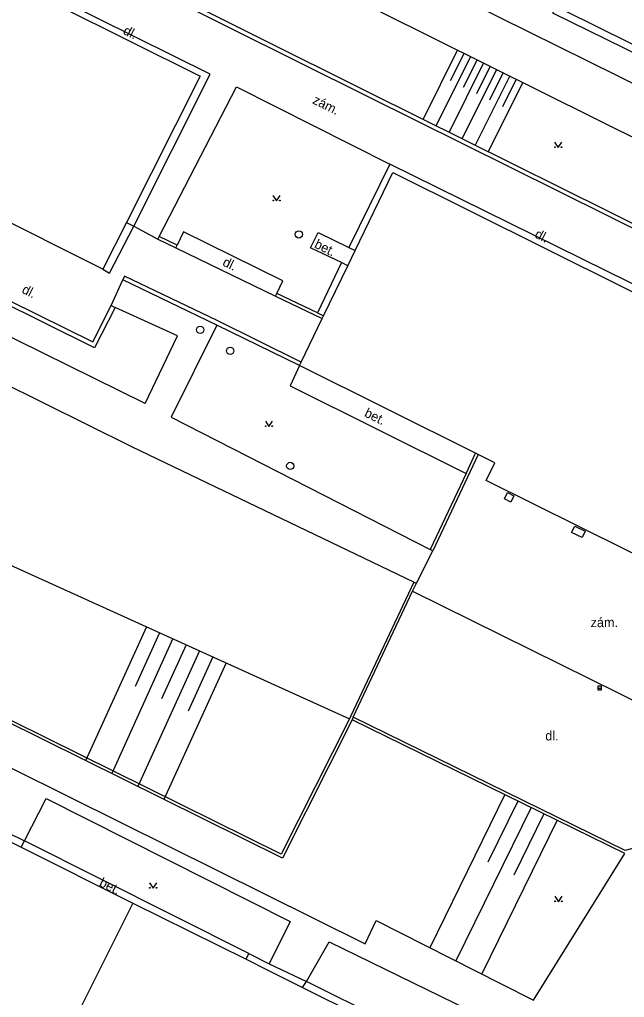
# Model space of a CAD drawing. Extents: x -602419 to -601554, y -1162937 to -1162362.
# Drawn here: x -602116.3 to -602074.8, y -1162567.9 to -1162500.8 of the extents above; entities that cross this region are included whole.
import ezdxf

# ---------------------------------------------------------------- set-up
doc = ezdxf.new("R2010")
doc.units = 0
doc.layers.add('Podklad', color=7, linetype='Continuous')

msp = doc.modelspace()

# ---------------------------------------------------------------- linework, layer by layer
at = {"layer": 'Podklad'}
msp.add_line((-602076.615, -1162546.67), (-602076.365, -1162546.67), dxfattribs=at)
for points in [[(-602089.26, -1162539.4), (-602108.58, -1162530.12), (-602154.26, -1162507.48), (-602198.48, -1162485.59), (-602249.5, -1162460.39)], [(-602093.5, -1162548.86), (-602098.27, -1162558.35), (-602128.4, -1162543.44), (-602175.25, -1162520.19), (-602211.34, -1162502.17), (-602258.9099, -1162478.56)], [(-602113.88, -1162489.1), (-602073.08, -1162509.4099)], [(-602072.35, -1162503.94), (-602079.7, -1162500.33), (-602078.6, -1162498.12), (-602081.55, -1162496.61), (-602082.2199, -1162497.76), (-602085.09, -1162496.3), (-602088.1599, -1162494.82), (-602087.5, -1162493.6599), (-602090.6, -1162492.15), (-602091.74, -1162494.33), (-602098.88, -1162490.82)], [(-602073.2, -1162505.6599), (-602099.7199, -1162492.51)], [(-602116.15, -1162493.87), (-602092.27, -1162505.8), (-602069.33, -1162517.19)], [(-602116.28, -1162494.14), (-602092.4099, -1162506.06), (-602069.46, -1162517.46)], [(-602209.38, -1162496.3), (-602093.68, -1162548.78)], [(-602103.24, -1162504.51), (-602113.5, -1162499.44)], [(-602113.68, -1162499.8), (-602103.92, -1162504.65)], [(-602072.14, -1162503.51), (-602078.94, -1162500.14)], [(-602086.26, -1162502.85), (-602088.62, -1162507.61)], [(-602085.36, -1162503.3), (-602087.73, -1162508.05)], [(-602085.81, -1162503.07), (-602086.76, -1162504.98)], [(-602084.4699, -1162503.74), (-602086.83, -1162508.5)], [(-602084.9099, -1162503.52), (-602085.86, -1162505.42)], [(-602084.02, -1162503.96), (-602084.96, -1162505.87)], [(-602103.92, -1162504.65), (-602108.98, -1162514.7)], [(-602108.49, -1162514.96), (-602103.24, -1162504.51)], [(-602083.57, -1162504.19), (-602085.94, -1162508.94)], [(-602082.67, -1162504.63), (-602085.04, -1162509.39)], [(-602083.12, -1162504.4099), (-602084.07, -1162506.31)], [(-602106.73, -1162515.6599), (-602101.43, -1162505.38), (-602090.9099, -1162510.7)], [(-602081.78, -1162505.08), (-602084.15, -1162509.83)], [(-602082.23, -1162504.86), (-602083.17, -1162506.76)], [(-602079.59, -1162509.185), (-602079.34, -1162509.56), (-602079.09, -1162509.185)], [(-602090.9099, -1162510.7), (-602093.7199, -1162516.4099)], [(-602071.18, -1162520.42), (-602090.9099, -1162510.7)], [(-602093.28, -1162516.62), (-602090.69, -1162511.26)], [(-602090.69, -1162511.26), (-602074.83, -1162519.1599)], [(-602098.93, -1162512.8449), (-602098.68, -1162513.2199), (-602098.43, -1162512.8449)], [(-602109.77, -1162520.53), (-602111.17, -1162523.3), (-602121.26, -1162518.32), (-602118.9699, -1162513.73)], [(-602118.7, -1162513.86), (-602120.86, -1162518.18), (-602111.3, -1162522.9), (-602110.04, -1162520.4)], [(-602110.6, -1162517.9), (-602118.7, -1162513.86)], [(-602108.98, -1162514.7), (-602110.6, -1162517.9)], [(-602108.98, -1162514.7), (-602108.49, -1162514.96)], [(-602110.6, -1162517.9), (-602110.16, -1162518.1899), (-602108.49, -1162514.96)], [(-602108.49, -1162514.96), (-602106.83, -1162515.84)], [(-602098.6599, -1162519.57), (-602098.24, -1162518.7), (-602105.07, -1162515.35), (-602105.51, -1162516.26)], [(-602096.36, -1162516.44), (-602095.83, -1162515.39)], [(-602095.83, -1162515.39), (-602093.7199, -1162516.4099)], [(-602106.83, -1162515.84), (-602106.73, -1162515.6599)], [(-602106.83, -1162515.84), (-602105.59, -1162516.44)], [(-602105.51, -1162516.26), (-602106.73, -1162515.6599)], [(-602107.69, -1162527.13), (-602128.83, -1162516.71)], [(-602105.59, -1162516.44), (-602105.51, -1162516.26)], [(-602105.59, -1162516.44), (-602098.75, -1162519.75)], [(-602094.23, -1162517.46), (-602096.36, -1162516.44)], [(-602093.79, -1162517.67), (-602093.28, -1162516.62)], [(-602093.7199, -1162516.4099), (-602093.28, -1162516.62)], [(-602094.23, -1162517.46), (-602095.88, -1162520.9099)], [(-602093.79, -1162517.67), (-602094.23, -1162517.46)], [(-602095.45, -1162521.12), (-602093.79, -1162517.67)], [(-602110.04, -1162520.4), (-602109.24, -1162518.65)], [(-602097, -1162524.29), (-602102.76, -1162521.44), (-602109.11, -1162518.38), (-602109.24, -1162518.65)], [(-602102.79, -1162521.76), (-602109.24, -1162518.65)], [(-602098.75, -1162519.75), (-602098.6599, -1162519.57)], [(-602095.88, -1162520.9099), (-602098.6599, -1162519.57)], [(-602074.83, -1162519.1599), (-602071.39, -1162520.87)], [(-602098.75, -1162519.75), (-602095.54, -1162521.3)], [(-602110.04, -1162520.4), (-602109.77, -1162520.53)], [(-602107.69, -1162527.13), (-602105.49, -1162522.48), (-602109.77, -1162520.53)], [(-602095.88, -1162520.9099), (-602095.45, -1162521.12)], [(-602097, -1162524.29), (-602095.54, -1162521.3)], [(-602095.54, -1162521.3), (-602095.45, -1162521.12)], [(-602102.79, -1162521.76), (-602105.92, -1162528.06)], [(-602097.11, -1162524.53), (-602102.79, -1162521.76)], [(-602097.11, -1162524.53), (-602097, -1162524.29)], [(-602097.11, -1162524.53), (-602097.74, -1162525.93), (-602085.67, -1162531.93)], [(-602085.02, -1162530.54), (-602097.11, -1162524.53)], [(-602105.92, -1162528.06), (-602088.13, -1162537.15)], [(-602099.45, -1162528.335), (-602099.2, -1162528.71), (-602098.95, -1162528.335)], [(-602084.84, -1162530.63), (-602087.95, -1162537.24)], [(-602085.67, -1162531.93), (-602085.02, -1162530.54)], [(-602084.84, -1162530.63), (-602085.02, -1162530.54)], [(-602083.69, -1162531.2), (-602084.84, -1162530.63)], [(-602084.29, -1162532.42), (-602083.69, -1162531.2)], [(-602085.67, -1162531.93), (-602088.13, -1162537.15)], [(-602064.98, -1162542.02), (-602084.29, -1162532.42)], [(-602083.04, -1162533.68), (-602082.82, -1162533.25)], [(-602082.59, -1162533.9), (-602083.04, -1162533.68)], [(-602082.82, -1162533.25), (-602082.38, -1162533.48)], [(-602082.38, -1162533.48), (-602082.59, -1162533.9)], [(-602093.68, -1162548.78), (-602098.36, -1162558.08), (-602128.31, -1162543.26), (-602144.32, -1162535.29)], [(-602078.42, -1162535.98), (-602078.2, -1162535.55)], [(-602078.2, -1162535.55), (-602077.49, -1162535.9)], [(-602077.7, -1162536.33), (-602078.42, -1162535.98)], [(-602077.49, -1162535.9), (-602077.7, -1162536.33)], [(-602089.08, -1162539.48), (-602087.95, -1162537.24)], [(-602087.95, -1162537.24), (-602088.13, -1162537.15)], [(-602089.26, -1162539.4), (-602093.59, -1162548.59)], [(-602089.34, -1162540.03), (-602089.08, -1162539.48)], [(-602089.26, -1162539.4), (-602089.08, -1162539.48)], [(-602093.4099, -1162548.68), (-602089.34, -1162540.03)], [(-602089.34, -1162540.03), (-602065, -1162552.05)], [(-602107.62, -1162542.46), (-602111.79, -1162551.6599)], [(-602106.71, -1162542.87), (-602108.38, -1162546.56)], [(-602105.8, -1162543.28), (-602110, -1162552.55)], [(-602104.89, -1162543.7), (-602106.57, -1162547.4099)], [(-602103.98, -1162544.11), (-602108.2, -1162553.43)], [(-602102.15, -1162544.93), (-602106.4099, -1162554.32)], [(-602103.06, -1162544.52), (-602104.76, -1162548.26)], [(-602127.92, -1162546.68), (-602116.73, -1162552.24), (-602109.33, -1162555.92), (-602099.5, -1162560.8), (-602092.6, -1162564.23), (-602091.84, -1162562.64), (-602083.31, -1162566.96)], [(-602093.59, -1162548.59), (-602093.68, -1162548.78)], [(-602093.4099, -1162548.68), (-602093.5, -1162548.86)], [(-602074.76, -1162558.03), (-602093.5, -1162548.86)], [(-602065, -1162552.05), (-602066.68, -1162555.65), (-602074.74, -1162557.83), (-602093.4099, -1162548.68)], [(-602115.99, -1162557.1599), (-602114.5, -1162554.25)], [(-602114.5, -1162554.25), (-602097.74, -1162562.71), (-602099.18, -1162565.61)], [(-602083.01, -1162553.99), (-602088.15, -1162564.51)], [(-602082.11, -1162554.43), (-602084.17, -1162558.64)], [(-602081.21, -1162554.87), (-602086.37, -1162565.4099)], [(-602120.15, -1162555.6599), (-602116.2199, -1162557.61)], [(-602079.42, -1162555.75), (-602084.58, -1162566.31)], [(-602080.32, -1162555.31), (-602082.38, -1162559.53)], [(-602118.34, -1162556.02), (-602115.99, -1162557.1599)], [(-602116.2199, -1162557.61), (-602115.99, -1162557.1599)], [(-602100.58, -1162564.9099), (-602115.99, -1162557.1599)], [(-602116.2199, -1162557.61), (-602108.54, -1162561.44)], [(-602081.05, -1162568.1), (-602074.76, -1162558.03)], [(-602107.4, -1162560.045), (-602107.15, -1162560.42), (-602106.9, -1162560.045)], [(-602079.572, -1162560.971), (-602079.322, -1162561.346), (-602079.072, -1162560.971)], [(-602108.54, -1162561.44), (-602114.03, -1162572.44)], [(-602108.54, -1162561.44), (-602100.77, -1162565.3)], [(-602096.62, -1162566.82), (-602095.06, -1162564.09), (-602077.86, -1162572.5), (-602079.42, -1162575.38)], [(-602100.77, -1162565.3), (-602100.58, -1162564.9099)], [(-602100.58, -1162564.9099), (-602099.18, -1162565.61)], [(-602100.77, -1162565.3), (-602099.24, -1162566.06)], [(-602099.18, -1162565.61), (-602096.62, -1162566.82)], [(-602099.24, -1162566.06), (-602096.89, -1162567.23)], [(-602096.89, -1162567.23), (-602096.62, -1162566.82)], [(-602096.89, -1162567.23), (-602089.03, -1162571.15)], [(-602080.89, -1162574.65), (-602096.62, -1162566.82)], [(-602083.31, -1162566.96), (-602081.05, -1162568.1)]]:
    msp.add_lwpolyline(points, dxfattribs=at)
msp.add_lwpolyline([(-602076.615, -1162546.795), (-602076.365, -1162546.795), (-602076.365, -1162546.545), (-602076.615, -1162546.545)], close=True, dxfattribs=at)
for centre, radius in [((-602079.5651, -1162509.5349), 0.025), ((-602079.1154, -1162509.5349), 0.025), ((-602098.9051, -1162513.1948), 0.025), ((-602098.4554, -1162513.1948), 0.025), ((-602097.15, -1162515.52), 0.25), ((-602103.92, -1162522.07), 0.25), ((-602101.87, -1162523.52), 0.25), ((-602099.4251, -1162528.6849), 0.025), ((-602098.9754, -1162528.6849), 0.025), ((-602097.74, -1162531.42), 0.25), ((-602107.3751, -1162560.3949), 0.025), ((-602106.9254, -1162560.3949), 0.025), ((-602079.5471, -1162561.3209), 0.025), ((-602079.0974, -1162561.3209), 0.025)]:
    msp.add_circle(centre, radius, dxfattribs=at)

# ---------------------------------------------------------------- texts
for s, rotation, p in [('dl.', 333.04, (-602109.27, -1162501.73)), (' zám.', 333.64, (-602096.48, -1162506.39)), ('dl.', 333.04, (-602081.01, -1162515.7)), ('bet.', 333.64, (-602096.14, -1162516.4)), ('dl.', 333.64, (-602102.44, -1162517.63)), ('dl.', 333.64, (-602116.2199, -1162519.51)), ('bet.', 333.64, (-602092.71, -1162527.99)), ('bet.', 333.58, (-602110.9099, -1162560.24))]:
    msp.add_text(s, height=0.65, rotation=rotation, dxfattribs=at).set_placement(p)
for s, p in [(' zám.', (-602077.36, -1162542.49)), ('dl.', (-602080.23, -1162550.27))]:
    msp.add_text(s, height=0.65, dxfattribs=at).set_placement(p)

doc.saveas('drawing.dxf')
